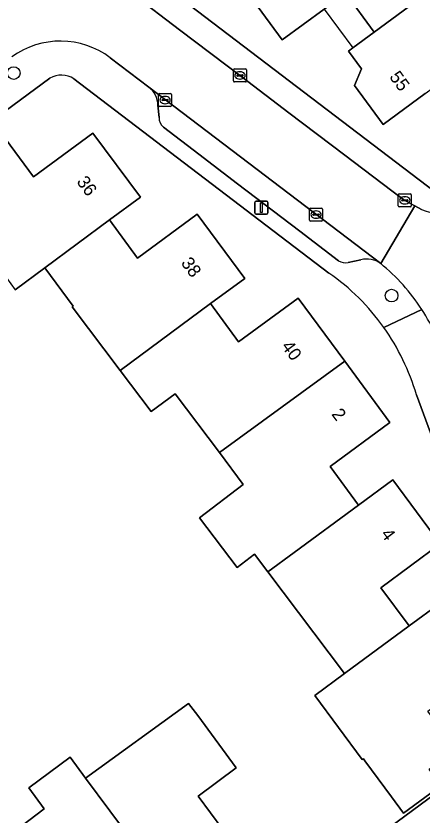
# Model space of a CAD drawing. Extents: x 163426 to 164192, y 380329 to 381641.
# Drawn here: x 163816.4 to 163847.7, y 381284.8 to 381346.5 of the extents above; entities that cross this region are included whole.
import ezdxf

# ---------------------------------------------------------------- set-up
doc = ezdxf.new("R2010")
doc.units = 0
for name, color, linetype in [('IMGEO_Boom', 7, 'Continuous'), ('IMGEO_Erf', 7, 'Continuous'), ('IMGEO_Kolk', 7, 'Continuous'), ('IMGEO_Lichtmast', 7, 'Continuous'), ('IMGEO_Pand', 7, 'Continuous'), ('IMGEO_Pand_nummerreeks', 7, 'Continuous'), ('IMGEO_Pand_overbouw', 7, 'Continuous'), ('IMGEO_Parkeervlak_open', 7, 'Continuous'), ('IMGEO_Rijbaan_lokaal_open', 7, 'Continuous'), ('IMGEO_Voetpad_open', 7, 'Continuous')]:
    doc.layers.add(name, color=color, linetype=linetype)

msp = doc.modelspace()

# ---------------------------------------------------------------- linework, layer by layer
at = {"layer": 'IMGEO_Boom'}
for centre in [(163816.183, 381342.055), (163845.32, 381324.894)]:
    msp.add_circle(centre, 0.489, dxfattribs=at)
at = {"layer": 'IMGEO_Erf'}
for points in [[(163823.242, 381352.26), (163825.625, 381350.446), (163848.628, 381332.932)], [(163847.921, 381340.472), (163844.68, 381338.083), (163842.458, 381341.102), (163843.005, 381342.374), (163841.998, 381343.736), (163842.343, 381343.991), (163843.989, 381345.207), (163841.784, 381348.207)], [(163840.127, 381346.989), (163836.894, 381344.613), (163834.667, 381347.634)], [(163818.972, 381341.665), (163756.006, 381295.168)], [(163840.491, 381326.631), (163820.821, 381341.611)], [(163815.54, 381336.99), (163817.706, 381334.047), (163822.29, 381337.42), (163825.95, 381332.49), (163823.568, 381330.736), (163825.743, 381327.782), (163830.33, 381331.16), (163834, 381326.22), (163831.359, 381324.288), (163833.52, 381321.333), (163838.11, 381324.69), (163841.707, 381319.83), (163845.2, 381315.11), (163840.58, 381311.706), (163842.771, 381308.731), (163845.43, 381310.69), (163849.08, 381305.74), (163844.5, 381302.367), (163846.672, 381299.419), (163849.064, 381301.18)], [(163849.152, 381287.121), (163846.24, 381284.983), (163845.32, 381286.23), (163843.272, 381289.006), (163843.147, 381289.175), (163843.059, 381289.109), (163839.408, 381294.058), (163841.7, 381295.75), (163835.789, 381303.577), (163834.757, 381304.944), (163833.407, 381303.924), (163830.506, 381307.766), (163833.888, 381310.319), (163832.045, 381312.78), (163828.64, 381317.326), (163826.774, 381315.948), (163824.388, 381319.109), (163820.684, 381324.017), (163820.772, 381324.083), (163818.594, 381327.036), (163816.301, 381325.344)], [(163855.999, 381293.46), (163847.238, 381317.241)], [(163813.881, 381281.791), (163818.532, 381285.323), (163817.341, 381286.93), (163820.529, 381289.294), (163821.722, 381287.688), (163829.674, 381293.448), (163830.375, 381292.498), (163833.341, 381288.473), (163830.403, 381286.299), (163833.262, 381282.437)], [(163791.55, 381244.263), (163799.315, 381250), (163855.325, 381291.38)]]:
    msp.add_lwpolyline(points, dxfattribs=at)
for centre, radius, start, end in [((163819.851, 381340.075), 1.816, 57.71693, 118.93738), ((163830.542, 381312.366), 17.392, 35.38181, 55.10778), ((163830.554, 381312.367), 17.381, 16.28349, 35.39942)]:
    msp.add_arc(centre, radius, start, end, dxfattribs=at)
at = {"layer": 'IMGEO_Kolk'}
for p, q in [((163833.209, 381342.368), (163834.061, 381342.368)), ((163833.134, 381341.442), (163833.134, 381342.294)), ((163833.393, 381341.862), (163833.393, 381341.874)), ((163833.831, 381341.825), (163833.433, 381341.825)), ((163833.436, 381341.911), (163833.834, 381341.911)), ((163833.622, 381342.148), (163833.647, 381342.148)), ((163833.877, 381341.874), (163833.877, 381341.862)), ((163834.135, 381342.294), (163834.135, 381341.442)), ((163834.061, 381341.368), (163833.209, 381341.368)), ((163833.645, 381341.588), (163833.62, 381341.588)), ((163827.359, 381339.542), (163827.359, 381340.394)), ((163827.434, 381340.468), (163828.286, 381340.468)), ((163827.618, 381339.962), (163827.618, 381339.974)), ((163828.056, 381339.925), (163827.658, 381339.925)), ((163827.661, 381340.011), (163828.059, 381340.011)), ((163827.847, 381340.248), (163827.872, 381340.248)), ((163828.102, 381339.974), (163828.102, 381339.962)), ((163828.36, 381340.394), (163828.36, 381339.542)), ((163828.286, 381339.468), (163827.434, 381339.468)), ((163827.87, 381339.688), (163827.845, 381339.688)), ((163845.844, 381331.81), (163845.844, 381332.662)), ((163845.919, 381332.736), (163846.771, 381332.736)), ((163846.332, 381332.516), (163846.357, 381332.516)), ((163846.845, 381332.662), (163846.845, 381331.81)), ((163846.103, 381332.23), (163846.103, 381332.242)), ((163846.541, 381332.193), (163846.143, 381332.193)), ((163846.146, 381332.279), (163846.544, 381332.279)), ((163846.355, 381331.956), (163846.33, 381331.956)), ((163846.587, 381332.242), (163846.587, 381332.23)), ((163838.999, 381330.713), (163838.999, 381331.565)), ((163839.074, 381331.639), (163839.926, 381331.639)), ((163839.487, 381331.419), (163839.512, 381331.419)), ((163840, 381331.565), (163840, 381330.713)), ((163846.771, 381331.736), (163845.919, 381331.736)), ((163839.926, 381330.639), (163839.074, 381330.639)), ((163839.258, 381331.133), (163839.258, 381331.145)), ((163839.696, 381331.096), (163839.298, 381331.096)), ((163839.301, 381331.182), (163839.699, 381331.182)), ((163839.51, 381330.859), (163839.485, 381330.859)), ((163839.742, 381331.145), (163839.742, 381331.133))]:
    msp.add_line(p, q, dxfattribs=at)
for points in [[(163833.209, 381342.368), (163834.061, 381342.368)], [(163833.134, 381341.442), (163833.134, 381342.294)], [(163834.135, 381342.294), (163834.135, 381341.442)], [(163834.061, 381341.368), (163833.209, 381341.368)], [(163827.359, 381339.542), (163827.359, 381340.394)], [(163827.434, 381340.468), (163828.286, 381340.468)], [(163828.36, 381340.394), (163828.36, 381339.542)], [(163828.286, 381339.468), (163827.434, 381339.468)], [(163845.844, 381331.81), (163845.844, 381332.662)], [(163845.919, 381332.736), (163846.771, 381332.736)], [(163846.845, 381332.662), (163846.845, 381331.81)], [(163838.999, 381330.713), (163838.999, 381331.565)], [(163839.074, 381331.639), (163839.926, 381331.639)], [(163840, 381331.565), (163840, 381330.713)], [(163846.771, 381331.736), (163845.919, 381331.736)], [(163839.926, 381330.639), (163839.074, 381330.639)]]:
    msp.add_lwpolyline(points, dxfattribs=at)
for centre, radius, start, end in [((163833.211, 381342.292), 0.0765, 91.55205, 178.44795), ((163833.211, 381342.292), 0.0765, 91.55205, 178.44795), ((163834.059, 381342.292), 0.0765, 1.55205, 88.44795), ((163834.059, 381342.292), 0.0765, 1.55205, 88.44795), ((163833.433, 381341.871), 0.0403, 85.87752, 175.75265), ((163833.43, 381341.861), 0.0366, 178.93798, 274.71019), ((163833.834, 381341.868), 0.043, 264.86636, 352.45326), ((163833.838, 381341.873), 0.0386, 1.73085, 96.63898), ((163833.211, 381341.444), 0.0765, 181.55205, 268.44795), ((163833.211, 381341.444), 0.0765, 181.55205, 268.44795), ((163834.059, 381341.444), 0.0765, 271.55205, 358.44795), ((163834.059, 381341.444), 0.0765, 271.55205, 358.44795), ((163827.436, 381340.392), 0.0765, 91.55205, 178.44795), ((163827.436, 381340.392), 0.0765, 91.55205, 178.44795), ((163827.658, 381339.971), 0.0403, 85.87752, 175.75265), ((163827.655, 381339.961), 0.0366, 178.93798, 274.71019), ((163828.059, 381339.968), 0.043, 264.86636, 352.45326), ((163828.063, 381339.973), 0.0386, 1.73085, 96.63898), ((163828.284, 381340.392), 0.0765, 1.55205, 88.44795), ((163828.284, 381340.392), 0.0765, 1.55205, 88.44795), ((163827.436, 381339.544), 0.0765, 181.55205, 268.44795), ((163827.436, 381339.544), 0.0765, 181.55205, 268.44795), ((163828.284, 381339.544), 0.0765, 271.55205, 358.44795), ((163828.284, 381339.544), 0.0765, 271.55205, 358.44795), ((163845.921, 381332.66), 0.0765, 91.55205, 178.44795), ((163845.921, 381332.66), 0.0765, 91.55205, 178.44795), ((163846.769, 381332.66), 0.0765, 1.55205, 88.44795), ((163846.769, 381332.66), 0.0765, 1.55205, 88.44795), ((163846.143, 381332.239), 0.0403, 85.87752, 175.75265), ((163846.14, 381332.229), 0.0366, 178.93798, 274.71019), ((163846.544, 381332.236), 0.043, 264.86636, 352.45326), ((163846.548, 381332.241), 0.0386, 1.73085, 96.63898), ((163839.076, 381331.563), 0.0765, 91.55205, 178.44795), ((163839.076, 381331.563), 0.0765, 91.55205, 178.44795), ((163839.924, 381331.563), 0.0765, 1.55205, 88.44795), ((163839.924, 381331.563), 0.0765, 1.55205, 88.44795), ((163845.921, 381331.812), 0.0765, 181.55205, 268.44795), ((163845.921, 381331.812), 0.0765, 181.55205, 268.44795), ((163846.769, 381331.812), 0.0765, 271.55205, 358.44795), ((163846.769, 381331.812), 0.0765, 271.55205, 358.44795), ((163839.076, 381330.715), 0.0765, 181.55205, 268.44795), ((163839.076, 381330.715), 0.0765, 181.55205, 268.44795), ((163839.298, 381331.142), 0.0403, 85.87752, 175.75265), ((163839.295, 381331.132), 0.0366, 178.93798, 274.71019), ((163839.699, 381331.139), 0.043, 264.86636, 352.45326), ((163839.703, 381331.144), 0.0386, 1.73085, 96.63898), ((163839.924, 381330.715), 0.0765, 271.55205, 358.44795), ((163839.924, 381330.715), 0.0765, 271.55205, 358.44795)]:
    msp.add_arc(centre, radius, start, end, dxfattribs=at)
for centre, major_axis, ratio, start_param, end_param in [((163833.621, 381341.868), (-0.387, 0.002), 0.722429, 4.712389, 7.853982), ((163833.646, 381341.868), (-0.39, 0.002), 0.717154, 1.570796, 4.712389), ((163827.846, 381339.968), (-0.387, 0.002), 0.722429, 4.712389, 7.853982), ((163827.871, 381339.968), (-0.39, 0.002), 0.717154, 1.570796, 4.712389), ((163846.331, 381332.236), (-0.387, 0.002), 0.722429, 4.712389, 7.853982), ((163846.356, 381332.236), (-0.39, 0.002), 0.717154, 1.570796, 4.712389), ((163839.486, 381331.139), (-0.387, 0.002), 0.722429, 4.712389, 7.853982), ((163839.511, 381331.139), (-0.39, 0.002), 0.717154, 1.570796, 4.712389)]:
    msp.add_ellipse(centre, major_axis=major_axis, ratio=ratio, start_param=start_param, end_param=end_param, dxfattribs=at)
at = {"layer": 'IMGEO_Lichtmast'}
for p, q in [((163834.787, 381331.269), (163834.787, 381332.069)), ((163834.787, 381332.069), (163834.787, 381331.269)), ((163834.887, 381332.169), (163835.677, 381332.169)), ((163835.677, 381332.169), (163834.887, 381332.169)), ((163835.777, 381332.069), (163835.777, 381331.269)), ((163835.777, 381331.269), (163835.777, 381332.069)), ((163835.677, 381331.169), (163834.887, 381331.169)), ((163834.887, 381331.169), (163835.677, 381331.169))]:
    msp.add_line(p, q, dxfattribs=at)
msp.add_lwpolyline([(163835.207, 381332.044), (163835.357, 381332.044), (163835.357, 381331.294), (163835.207, 381331.294), (163835.207, 381332.044)], dxfattribs=at)
for centre, start, end in [((163834.887, 381332.069), 90, 180), ((163834.887, 381332.069), 90, 180), ((163835.677, 381332.069), 0, 90), ((163835.677, 381332.069), 360, 90), ((163834.887, 381331.269), 180, 270), ((163834.887, 381331.269), 180, 270), ((163835.677, 381331.269), 270, 0), ((163835.677, 381331.269), 270, 0)]:
    msp.add_arc(centre, 0.1, start, end, dxfattribs=at)
at = {"layer": 'IMGEO_Pand'}
for points in [[(163851.183, 381350.525), (163851.093, 381350.647), (163847.179, 381355.948), (163846.213, 381355.235), (163844.342, 381357.768), (163843.378, 381357.055), (163836.172, 381351.729), (163834.538, 381350.522), (163834.208, 381350.278), (163835.217, 381348.91), (163834.667, 381347.634), (163836.894, 381344.613), (163840.127, 381346.989), (163841.784, 381348.207), (163843.989, 381345.207)], [(163858.423, 381344.76), (163854.984, 381349.417), (163854.018, 381348.705), (163852.147, 381351.238), (163851.183, 381350.525), (163843.989, 381345.207), (163842.343, 381343.991), (163841.998, 381343.736), (163843.005, 381342.374), (163842.458, 381341.102), (163844.68, 381338.083), (163847.921, 381340.472), (163849.188, 381341.406), (163849.87, 381340.48), (163850.385, 381340.86), (163854.319, 381335.523), (163861.393, 381340.737)], [(163818.594, 381327.036), (163823.568, 381330.736), (163825.95, 381332.49), (163822.29, 381337.42), (163817.706, 381334.047), (163815.54, 381336.99), (163815.466, 381336.935), (163811.591, 381334.072), (163810.56, 381333.31), (163812.739, 381330.357), (163812.65, 381330.292), (163815.619, 381326.269), (163816.301, 381325.344)], [(163831.359, 381324.288), (163834, 381326.22), (163830.33, 381331.16), (163825.743, 381327.782), (163823.568, 381330.736), (163818.594, 381327.036), (163820.772, 381324.083), (163820.684, 381324.017), (163824.388, 381319.109)], [(163831.359, 381324.288), (163824.388, 381319.109), (163826.774, 381315.948), (163828.64, 381317.326), (163832.045, 381312.78), (163841.707, 381319.83), (163838.11, 381324.69), (163833.52, 381321.333)], [(163845.2, 381315.11), (163841.707, 381319.83), (163832.045, 381312.78), (163833.888, 381310.319), (163830.506, 381307.766), (163833.407, 381303.924), (163834.757, 381304.944), (163835.789, 381303.577), (163837.817, 381305.073), (163842.771, 381308.731), (163840.58, 381311.706)], [(163842.771, 381308.731), (163837.817, 381305.073), (163835.789, 381303.577), (163841.7, 381295.75), (163846.672, 381299.419), (163844.5, 381302.367), (163849.08, 381305.74), (163845.43, 381310.69)], [(163841.7, 381295.75), (163839.408, 381294.058), (163843.059, 381289.109), (163843.147, 381289.175), (163843.272, 381289.006), (163845.32, 381286.23), (163846.24, 381284.983), (163849.152, 381287.121), (163848.235, 381288.371), (163850.29, 381289.88), (163848.117, 381292.833), (163852.716, 381296.218), (163849.064, 381301.18), (163846.672, 381299.419)], [(163821.722, 381287.688), (163825.467, 381282.646), (163828.853, 381278.071), (163833.789, 381281.724), (163833.262, 381282.437), (163830.403, 381286.299), (163833.341, 381288.473), (163830.375, 381292.498), (163829.674, 381293.448)], [(163817.591, 381276.805), (163820.971, 381272.238), (163825.907, 381275.891), (163822.521, 381280.466), (163825.467, 381282.646), (163821.722, 381287.688), (163820.529, 381289.294), (163817.341, 381286.93), (163818.532, 381285.323), (163813.881, 381281.791)]]:
    msp.add_lwpolyline(points, close=True, dxfattribs=at)
at = {"layer": 'IMGEO_Pand_overbouw'}
msp.add_lwpolyline([(163841.784, 381348.207), (163840.127, 381346.989), (163842.343, 381343.991), (163843.989, 381345.207)], close=True, dxfattribs=at)
at = {"layer": 'IMGEO_Parkeervlak_open'}
for points in [[(163844.483, 381327.364), (163826.617, 381340.957)], [(163827.311, 381339.573), (163827.402, 381338.626)], [(163827.725, 381337.873), (163830.461, 381335.787), (163833.447, 381333.51), (163838.237, 381329.859), (163841.225, 381327.581)], [(163841.979, 381327.435), (163842.958, 381327.66)]]:
    msp.add_lwpolyline(points, dxfattribs=at)
for centre, radius, start, end in [((163825.539, 381339.55), 1.772, 0.73385, 52.52865), ((163828.274, 381338.554), 0.875, 175.28273, 231.15118), ((163841.792, 381328.487), 1.069, 237.97938, 280.10305), ((163843.401, 381325.865), 1.848, 54.16781, 103.86333)]:
    msp.add_arc(centre, radius, start, end, dxfattribs=at)
at = {"layer": 'IMGEO_Rijbaan_lokaal_open'}
for points in [[(163823.63, 381343.238), (163826.617, 381340.957), (163844.483, 381327.364), (163847.129, 381331.806), (163846.34, 381332.235), (163845.337, 381332.963), (163841.708, 381335.712), (163837.394, 381338.979), (163833.814, 381341.749), (163828.978, 381345.395), (163825.388, 381348.15), (163824.706, 381348.659), (163824.586, 381348.754), (163824.446, 381348.823)], [(163847.639, 381331.529), (163847.129, 381331.806), (163844.483, 381327.364)]]:
    msp.add_lwpolyline(points, dxfattribs=at)
for centre, radius, start, end in [((163819.796, 381338.133), 6.385, 53.09594, 125.93668), ((163849.836, 381337.116), 6.003, 248.53582, 305.70431), ((163834.895, 381315.597), 15.179, 32.79867, 50.82655), ((163834.924, 381315.612), 15.146, 24.15511, 32.80973)]:
    msp.add_arc(centre, radius, start, end, dxfattribs=at)
at = {"layer": 'IMGEO_Voetpad_open'}
for points in [[(163848.628, 381332.932), (163825.625, 381350.446), (163825.138, 381349.755), (163824.446, 381348.823), (163824.586, 381348.754), (163824.706, 381348.659), (163825.388, 381348.15), (163828.978, 381345.395), (163833.814, 381341.749), (163837.394, 381338.979), (163841.708, 381335.712), (163845.337, 381332.963), (163846.34, 381332.235), (163847.129, 381331.806), (163847.639, 381331.529)], [(163826.617, 381340.957), (163823.63, 381343.238)], [(163756.006, 381295.168), (163818.972, 381341.665)], [(163820.821, 381341.611), (163840.491, 381326.631)], [(163827.402, 381338.626), (163827.311, 381339.573)], [(163841.225, 381327.581), (163838.237, 381329.859), (163833.447, 381333.51), (163830.461, 381335.787), (163827.725, 381337.873)], [(163842.958, 381327.66), (163841.979, 381327.435)], [(163847.654, 381323.819), (163844.722, 381322.436)], [(163844.722, 381322.436), (163847.654, 381323.819)], [(163847.238, 381317.241), (163855.999, 381293.46)], [(163855.325, 381291.38), (163799.315, 381250), (163791.55, 381244.263)]]:
    msp.add_lwpolyline(points, dxfattribs=at)
for centre, radius, start, end in [((163819.796, 381338.133), 6.385, 53.09594, 125.93668), ((163819.851, 381340.075), 1.816, 57.71693, 118.93738), ((163825.539, 381339.55), 1.772, 0.73385, 52.52865), ((163828.274, 381338.554), 0.875, 175.28273, 231.15118), ((163849.836, 381337.116), 6.003, 248.53582, 305.70431), ((163841.792, 381328.487), 1.069, 237.97938, 280.10305), ((163843.401, 381325.865), 1.848, 54.16781, 103.86333), ((163834.895, 381315.597), 15.179, 32.79867, 50.82655), ((163830.542, 381312.366), 17.392, 35.38181, 55.10778), ((163834.924, 381315.612), 15.146, 24.15511, 32.80973), ((163830.554, 381312.367), 17.381, 16.28349, 35.39942)]:
    msp.add_arc(centre, radius, start, end, dxfattribs=at)

# ---------------------------------------------------------------- texts
at = {"layer": 'IMGEO_Pand_nummerreeks'}
for s, rotation, p in [('55', 306.35396, (163845.109, 381341.752)), ('36', 306.58995, (163820.994, 381333.662)), ('38', 306.60921, (163829.041, 381327.395)), ('40', 306.50453, (163836.782, 381320.971)), ('2', 306.50293, (163840.652, 381315.742)), ('4', 306.40409, (163844.452, 381306.49))]:
    msp.add_text(s, height=1, rotation=rotation, dxfattribs=at).set_placement(p)

doc.saveas('drawing.dxf')
